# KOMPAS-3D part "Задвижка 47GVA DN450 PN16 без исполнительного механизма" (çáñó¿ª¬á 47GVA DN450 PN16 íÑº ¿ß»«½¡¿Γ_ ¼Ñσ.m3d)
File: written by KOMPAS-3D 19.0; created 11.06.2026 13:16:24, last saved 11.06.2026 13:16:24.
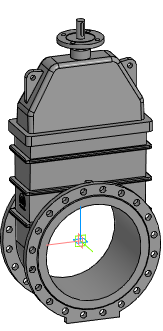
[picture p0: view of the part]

Document properties: Автор: Евгений; Полное имя файла: Z:\3.Личные\kachalov\001_3d для проектировщиков\2.2 Тип 47GVA, 47GVA.Z\_stp\_stp_Задвижка 47GVA DN40-DN1000 без исп.мех\Задвижка 47GVA DN450 PN16 без исполнит_ мех.m3d

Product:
- Part/product: Задвижка 47GVA DN450 PN16 без исполнительного механизма

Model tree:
1. Операция без истории:1  (labels: Задвижка 47GVA DN450 PN16 без исполнительного механизма)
